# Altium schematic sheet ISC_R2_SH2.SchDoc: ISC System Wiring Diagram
size C; DrawnBy: Filiberto Clara; Engineer: Filiberto Clara; Organization: LIGO Laboratory; Address1: California Institute of Technology; Address2: Massachusetts Institute of Technology; SheetNumber: 14; SheetTotal: 37
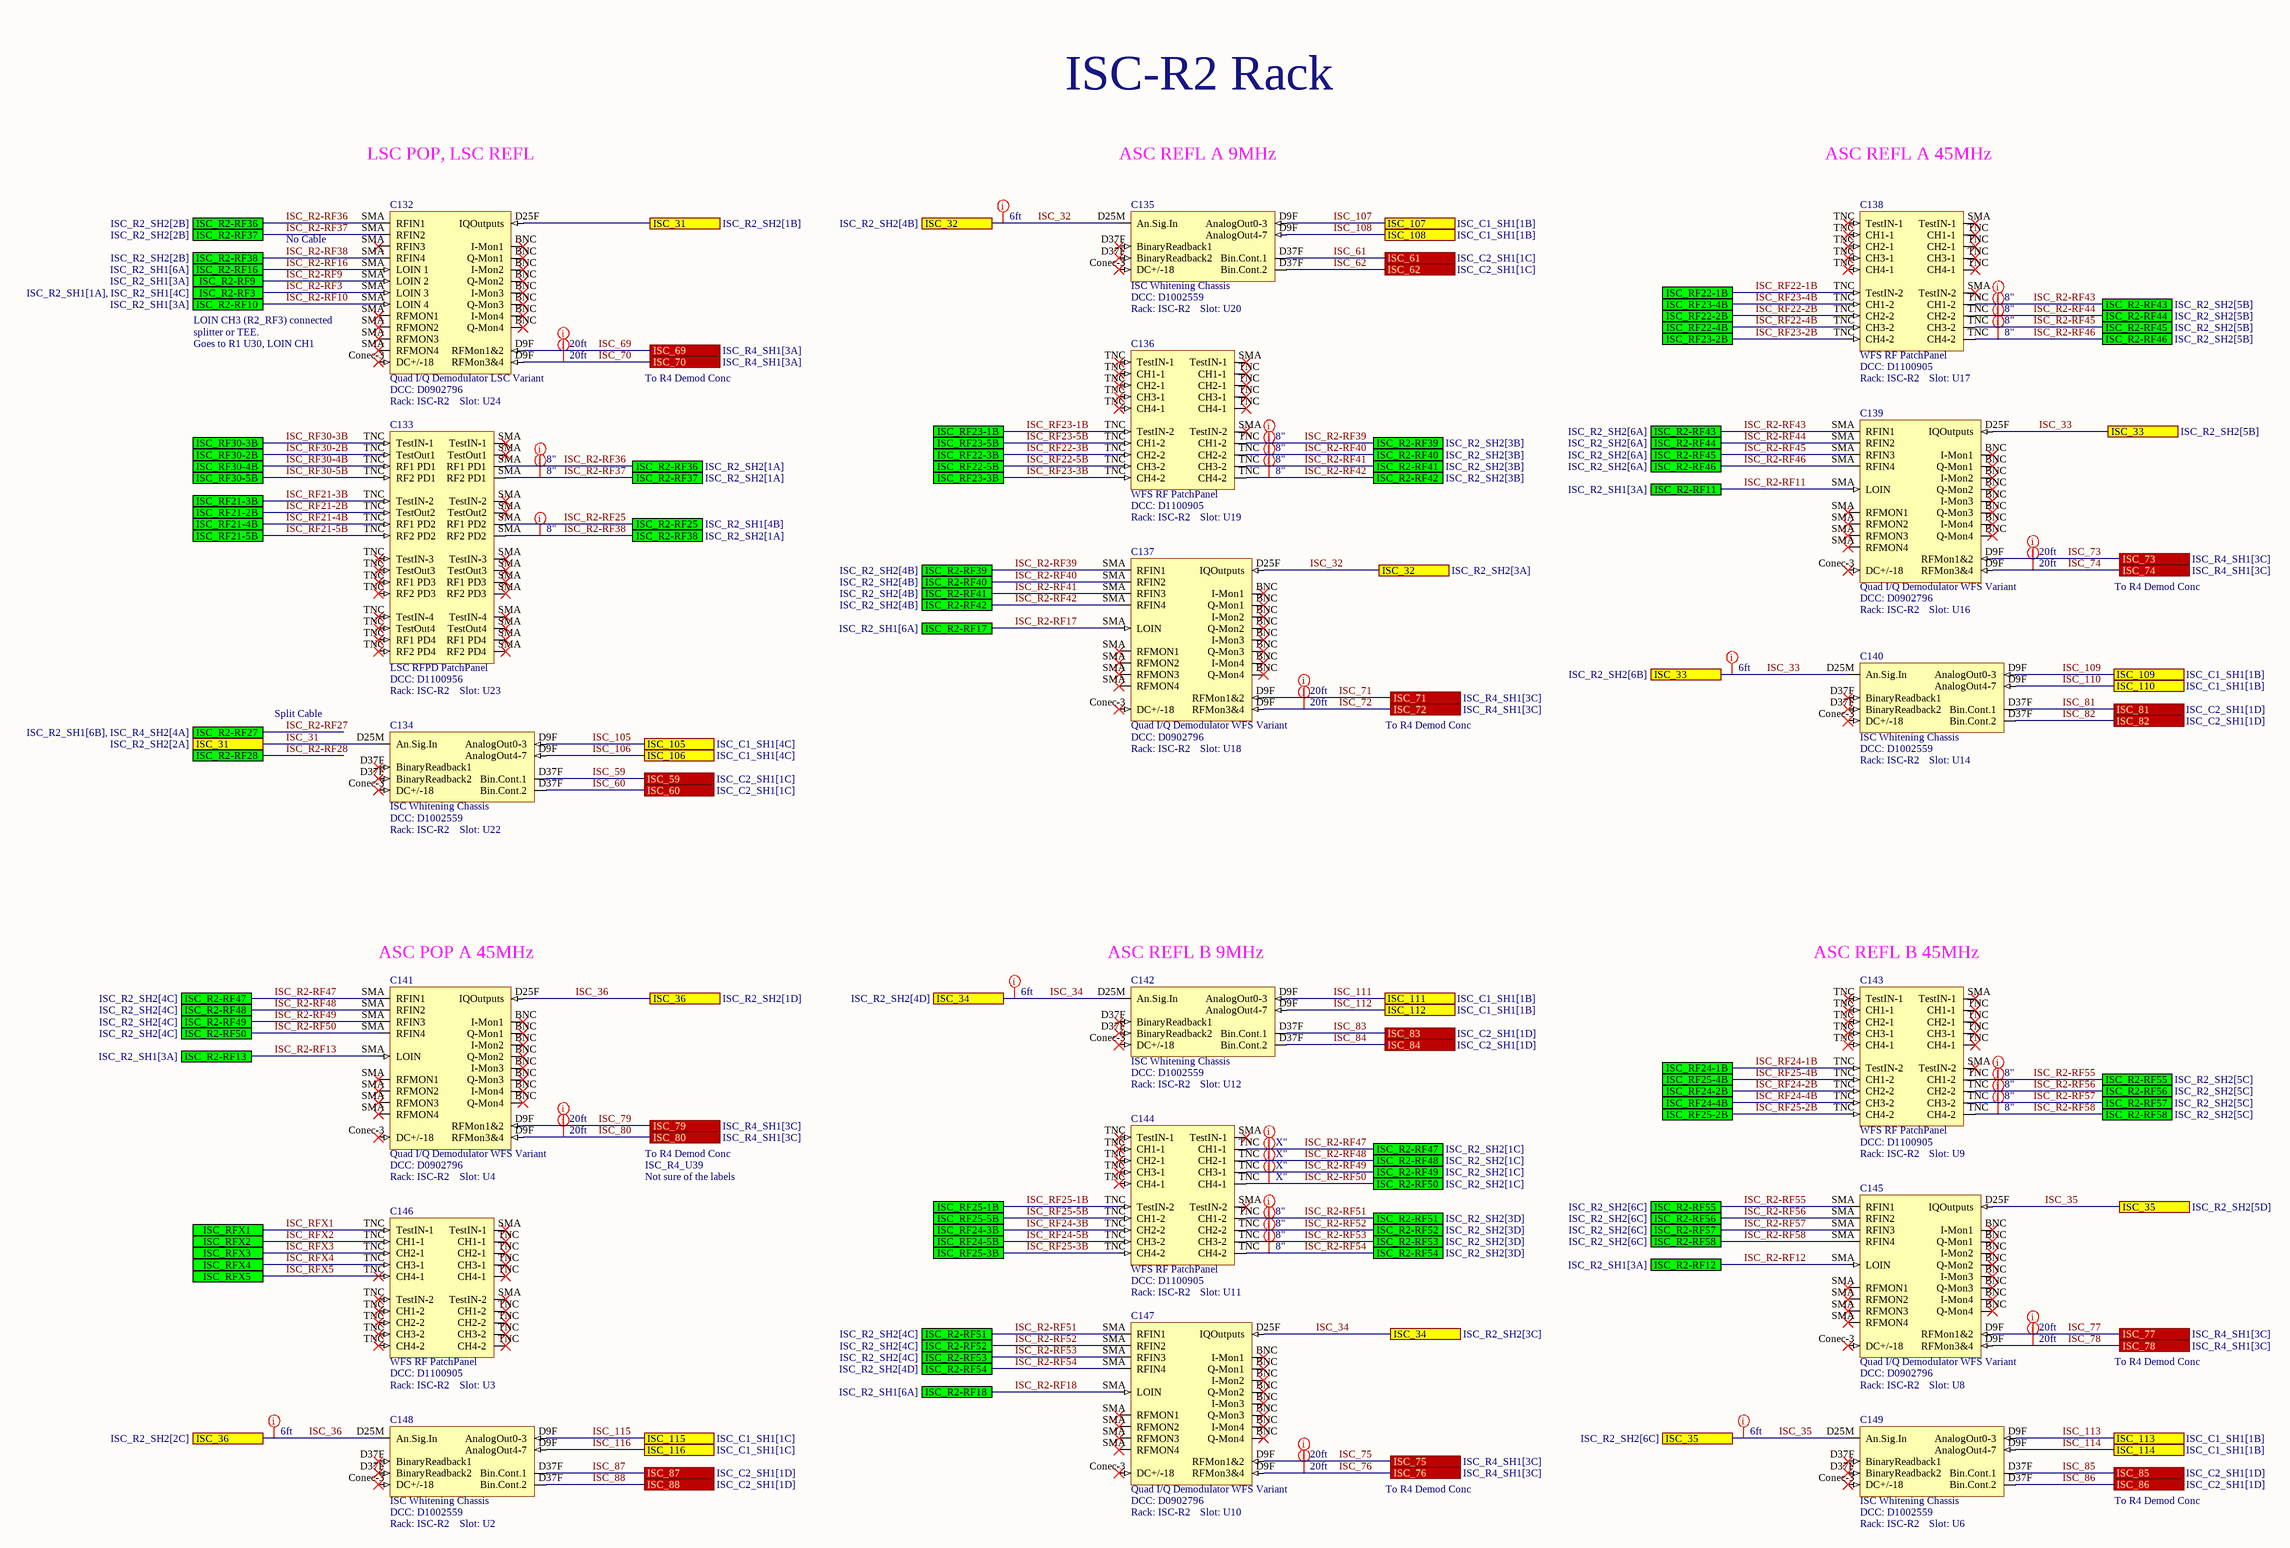
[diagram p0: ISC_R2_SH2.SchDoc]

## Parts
C132  Quad I/Q Demodulator LSC Variant  DCC: D0902796  Rack: ISC-R2  Slot: U24
C133  LSC RFPD PatchPanel  DCC: D1100956  Rack: ISC-R2  Slot: U23
C134  ISC Whitening Chassis  DCC: D1002559  Rack: ISC-R2  Slot: U22
C135  ISC Whitening Chassis  DCC: D1002559  Rack: ISC-R2  Slot: U20
C136  WFS RF PatchPanel  DCC: D1100905  Rack: ISC-R2  Slot: U19
C137  Quad I/Q Demodulator WFS Variant  DCC: D0902796  Rack: ISC-R2  Slot: U18
C138  WFS RF PatchPanel  DCC: D1100905  Rack: ISC-R2  Slot: U17
C139  Quad I/Q Demodulator WFS Variant  DCC: D0902796  Rack: ISC-R2  Slot: U16
C140  ISC Whitening Chassis  DCC: D1002559  Rack: ISC-R2  Slot: U14
C141  Quad I/Q Demodulator WFS Variant  DCC: D0902796  Rack: ISC-R2  Slot: U4
C142  ISC Whitening Chassis  DCC: D1002559  Rack: ISC-R2  Slot: U12
C143  WFS RF PatchPanel  DCC: D1100905  Rack: ISC-R2  Slot: U9
C144  WFS RF PatchPanel  DCC: D1100905  Rack: ISC-R2  Slot: U11
C145  Quad I/Q Demodulator WFS Variant  DCC: D0902796  Rack: ISC-R2  Slot: U8
C146  WFS RF PatchPanel  DCC: D1100905  Rack: ISC-R2  Slot: U3
C147  Quad I/Q Demodulator WFS Variant  DCC: D0902796  Rack: ISC-R2  Slot: U10
C148  ISC Whitening Chassis  DCC: D1002559  Rack: ISC-R2  Slot: U2
C149  ISC Whitening Chassis  DCC: D1002559  Rack: ISC-R2  Slot: U6

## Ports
ISC_31 (see ISC_R2_SH2[1B]), ISC_31 (see ISC_R2_SH2[2A]), ISC_32 (see ISC_R2_SH2[3A]), ISC_32 (see ISC_R2_SH2[4B]), ISC_33 (see ISC_R2_SH2[5B]), ISC_33 (see ISC_R2_SH2[6B]), ISC_34 (see ISC_R2_SH2[3C]), ISC_34 (see ISC_R2_SH2[4D]), ISC_35 (see ISC_R2_SH2[5D]), ISC_35 (see ISC_R2_SH2[6C]), ISC_36 (see ISC_R2_SH2[1D]), ISC_36 (see ISC_R2_SH2[2C]), ISC_59 (see ISC_C2_SH1[1C]), ISC_60 (see ISC_C2_SH1[1C]), ISC_61 (see ISC_C2_SH1[1C]), ISC_62 (see ISC_C2_SH1[1C]), ISC_69 (see ISC_R4_SH1[3A]), ISC_70 (see ISC_R4_SH1[3A]), ISC_71 (see ISC_R4_SH1[3C]), ISC_72 (see ISC_R4_SH1[3C]), ISC_73 (see ISC_R4_SH1[3C]), ISC_74 (see ISC_R4_SH1[3C]), ISC_75 (see ISC_R4_SH1[3C]), ISC_76 (see ISC_R4_SH1[3C]), ISC_77 (see ISC_R4_SH1[3C]), ISC_78 (see ISC_R4_SH1[3C]), ISC_79 (see ISC_R4_SH1[3C]), ISC_80 (see ISC_R4_SH1[3C]), ISC_81 (see ISC_C2_SH1[1D]), ISC_82 (see ISC_C2_SH1[1D]), ISC_83 (see ISC_C2_SH1[1D]), ISC_84 (see ISC_C2_SH1[1D]), ISC_85 (see ISC_C2_SH1[1D]), ISC_86 (see ISC_C2_SH1[1D]), ISC_87 (see ISC_C2_SH1[1D]), ISC_88 (see ISC_C2_SH1[1D]), ISC_105 (see ISC_C1_SH1[4C]), ISC_106 (see ISC_C1_SH1[4C]), ISC_107 (see ISC_C1_SH1[1B]), ISC_108 (see ISC_C1_SH1[1B]), ISC_109 (see ISC_C1_SH1[1B]), ISC_110 (see ISC_C1_SH1[1B]), ISC_111 (see ISC_C1_SH1[1B]), ISC_112 (see ISC_C1_SH1[1B]), ISC_113 (see ISC_C1_SH1[1B]), ISC_114 (see ISC_C1_SH1[1B]), ISC_115 (see ISC_C1_SH1[1C]), ISC_116 (see ISC_C1_SH1[1C]), ISC_R2-RF3 (see ISC_R2_SH1[1A], ISC_R2_SH1[4C]), ISC_R2-RF9 (see ISC_R2_SH1[3A]), ISC_R2-RF10 (see ISC_R2_SH1[3A]), ISC_R2-RF11 (see ISC_R2_SH1[3A]), ISC_R2-RF12 (see ISC_R2_SH1[3A]), ISC_R2-RF13 (see ISC_R2_SH1[3A]), ISC_R2-RF16 (see ISC_R2_SH1[6A]), ISC_R2-RF17 (see ISC_R2_SH1[6A]), ISC_R2-RF18 (see ISC_R2_SH1[6A]), ISC_R2-RF25 (see ISC_R2_SH1[4B]), ISC_R2-RF27 (see ISC_R2_SH1[6B], ISC_R4_SH2[4A]), ISC_R2-RF28, ISC_R2-RF36 (see ISC_R2_SH2[1A]), ISC_R2-RF36 (see ISC_R2_SH2[2B]), ISC_R2-RF37 (see ISC_R2_SH2[1A]), ISC_R2-RF37 (see ISC_R2_SH2[2B]), ISC_R2-RF38 (see ISC_R2_SH2[1A]), ISC_R2-RF38 (see ISC_R2_SH2[2B]), ISC_R2-RF39 (see ISC_R2_SH2[3B]), ISC_R2-RF39 (see ISC_R2_SH2[4B]), ISC_R2-RF40 (see ISC_R2_SH2[3B]), ISC_R2-RF40 (see ISC_R2_SH2[4B]), ISC_R2-RF41 (see ISC_R2_SH2[3B]), ISC_R2-RF41 (see ISC_R2_SH2[4B]), ISC_R2-RF42 (see ISC_R2_SH2[3B]), ISC_R2-RF42 (see ISC_R2_SH2[4B]), ISC_R2-RF43 (see ISC_R2_SH2[5B]), ISC_R2-RF43 (see ISC_R2_SH2[6A]), ISC_R2-RF44 (see ISC_R2_SH2[5B]), ISC_R2-RF44 (see ISC_R2_SH2[6A]), ISC_R2-RF45 (see ISC_R2_SH2[5B]), ISC_R2-RF45 (see ISC_R2_SH2[6A]), ISC_R2-RF46 (see ISC_R2_SH2[5B]), ISC_R2-RF46 (see ISC_R2_SH2[6A]), ISC_R2-RF47 (see ISC_R2_SH2[1C]), ISC_R2-RF47 (see ISC_R2_SH2[4C]), ISC_R2-RF48 (see ISC_R2_SH2[1C]), ISC_R2-RF48 (see ISC_R2_SH2[4C]), ISC_R2-RF49 (see ISC_R2_SH2[1C]), ISC_R2-RF49 (see ISC_R2_SH2[4C]), ISC_R2-RF50 (see ISC_R2_SH2[1C]), ISC_R2-RF50 (see ISC_R2_SH2[4C]), ISC_R2-RF51 (see ISC_R2_SH2[3D]), ISC_R2-RF51 (see ISC_R2_SH2[4C]), ISC_R2-RF52 (see ISC_R2_SH2[3D]), ISC_R2-RF52 (see ISC_R2_SH2[4C]), ISC_R2-RF53 (see ISC_R2_SH2[3D]), ISC_R2-RF53 (see ISC_R2_SH2[4C]), ISC_R2-RF54 (see ISC_R2_SH2[3D]), ISC_R2-RF54 (see ISC_R2_SH2[4D]), ISC_R2-RF55 (see ISC_R2_SH2[5C]), ISC_R2-RF55 (see ISC_R2_SH2[6C]), ISC_R2-RF56 (see ISC_R2_SH2[5C]), ISC_R2-RF56 (see ISC_R2_SH2[6C]), ISC_R2-RF57 (see ISC_R2_SH2[5C]), ISC_R2-RF57 (see ISC_R2_SH2[6C]), ISC_R2-RF58 (see ISC_R2_SH2[5C]), ISC_R2-RF58 (see ISC_R2_SH2[6C]), ISC_RF21-2B, ISC_RF21-3B, ISC_RF21-4B, ISC_RF21-5B, ISC_RF22-1B, ISC_RF22-2B, ISC_RF22-3B, ISC_RF22-4B, ISC_RF22-5B, ISC_RF23-1B, ISC_RF23-2B, ISC_RF23-3B, ISC_RF23-4B, ISC_RF23-5B, ISC_RF24-1B, ISC_RF24-2B, ISC_RF24-3B, ISC_RF24-4B, ISC_RF24-5B, ISC_RF25-1B, ISC_RF25-2B, ISC_RF25-3B, ISC_RF25-4B, ISC_RF25-5B, ISC_RF30-2B, ISC_RF30-3B, ISC_RF30-4B, ISC_RF30-5B, ISC_RFX1, ISC_RFX2, ISC_RFX3, ISC_RFX4, ISC_RFX5

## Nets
ISC_31: C132.D25F(IQOutputs) C134.D25M(An.Sig.In) ; port ISC_31
ISC_32: C135.D25M(An.Sig.In) C137.D25F(IQOutputs) ; port ISC_32
ISC_33: C139.D25F(IQOutputs) C140.D25M(An.Sig.In) ; port ISC_33
ISC_34: C142.D25M(An.Sig.In) C147.D25F(IQOutputs) ; port ISC_34
ISC_35: C145.D25F(IQOutputs) C149.D25M(An.Sig.In) ; port ISC_35
ISC_36: C141.D25F(IQOutputs) C148.D25M(An.Sig.In) ; port ISC_36
ISC_59: C134.D37F(BinaryReadback1) ; port ISC_59
ISC_60: C134.D37F(Bin.Cont.2) ; port ISC_60
ISC_61: C135.D37F(BinaryReadback1) ; port ISC_61
ISC_62: C135.D37F(Bin.Cont.2) ; port ISC_62
ISC_69: C132.D9F(RFMon1&2) ; port ISC_69
ISC_70: C132.D9F(RFMon3&4) ; port ISC_70
ISC_71: C137.D9F(RFMon1&2) ; port ISC_71
ISC_72: C137.D9F(RFMon3&4) ; port ISC_72
ISC_73: C139.D9F(RFMon1&2) ; port ISC_73
ISC_74: C139.D9F(RFMon3&4) ; port ISC_74
ISC_75: C147.D9F(RFMon1&2) ; port ISC_75
ISC_76: C147.D9F(RFMon3&4) ; port ISC_76
ISC_77: C145.D9F(RFMon1&2) ; port ISC_77
ISC_78: C145.D9F(RFMon3&4) ; port ISC_78
ISC_79: C141.D9F(RFMon1&2) ; port ISC_79
ISC_80: C141.D9F(RFMon3&4) ; port ISC_80
ISC_81: C140.D37F(BinaryReadback1) ; port ISC_81
ISC_82: C140.D37F(Bin.Cont.2) ; port ISC_82
ISC_83: C142.D37F(BinaryReadback1) ; port ISC_83
ISC_84: C142.D37F(Bin.Cont.2) ; port ISC_84
ISC_85: C149.D37F(BinaryReadback1) ; port ISC_85
ISC_86: C149.D37F(Bin.Cont.2) ; port ISC_86
ISC_87: C148.D37F(BinaryReadback1) ; port ISC_87
ISC_88: C148.D37F(Bin.Cont.2) ; port ISC_88
ISC_105: C134.D9F(AnalogOut0-3) ; port ISC_105
ISC_106: C134.D9F(AnalogOut4-7) ; port ISC_106
ISC_107: C135.D9F(AnalogOut0-3) ; port ISC_107
ISC_108: C135.D9F(AnalogOut4-7) ; port ISC_108
ISC_109: C140.D9F(AnalogOut0-3) ; port ISC_109
ISC_110: C140.D9F(AnalogOut4-7) ; port ISC_110
ISC_111: C142.D9F(AnalogOut0-3) ; port ISC_111
ISC_112: C142.D9F(AnalogOut4-7) ; port ISC_112
ISC_113: C149.D9F(AnalogOut0-3) ; port ISC_113
ISC_114: C149.D9F(AnalogOut4-7) ; port ISC_114
ISC_115: C148.D9F(AnalogOut0-3) ; port ISC_115
ISC_116: C148.D9F(AnalogOut4-7) ; port ISC_116
ISC_R2-RF3: C132.SMA(LOIN_3) ; port ISC_R2-RF3
ISC_R2-RF9: C132.SMA(LOIN_2) ; port ISC_R2-RF9
ISC_R2-RF10: C132.SMA(LOIN_4) ; port ISC_R2-RF10
ISC_R2-RF11: C139.SMA(LOIN) ; port ISC_R2-RF11
ISC_R2-RF12: C145.SMA(LOIN) ; port ISC_R2-RF12
ISC_R2-RF13: C141.SMA(LOIN) ; port ISC_R2-RF13
ISC_R2-RF16: C132.SMA(LOIN_1) ; port ISC_R2-RF16
ISC_R2-RF17: C137.SMA(LOIN) ; port ISC_R2-RF17
ISC_R2-RF18: C147.SMA(LOIN) ; port ISC_R2-RF18
ISC_R2-RF25: C133.SMA(RF1_PD2) ; port ISC_R2-RF25
ISC_R2-RF36: C132.SMA(RFIN1) C133.SMA(TestIN-1) ; port ISC_R2-RF36
ISC_R2-RF37: C132.SMA(RFIN2) C133.SMA(RF2_PD1) ; port ISC_R2-RF37
ISC_R2-RF38: C132.SMA(RFIN4) C133.SMA(RF2_PD2) ; port ISC_R2-RF38
ISC_R2-RF39: C136.TNC(CH1-2) C137.SMA(RFIN1) ; port ISC_R2-RF39
ISC_R2-RF40: C136.TNC(CH2-2) C137.SMA(RFIN2) ; port ISC_R2-RF40
ISC_R2-RF41: C136.TNC(CH3-2) C137.SMA(RFIN3) ; port ISC_R2-RF41
ISC_R2-RF42: C136.TNC(CH4-2) C137.SMA(RFIN4) ; port ISC_R2-RF42
ISC_R2-RF43: C138.TNC(CH1-2) C139.SMA(RFIN1) ; port ISC_R2-RF43
ISC_R2-RF44: C138.TNC(CH2-2) C139.SMA(RFIN2) ; port ISC_R2-RF44
ISC_R2-RF45: C138.TNC(CH3-2) C139.SMA(RFIN3) ; port ISC_R2-RF45
ISC_R2-RF46: C138.TNC(CH4-2) C139.SMA(RFIN4) ; port ISC_R2-RF46
ISC_R2-RF47: C141.SMA(RFIN1) C144.TNC(CH1-1) ; port ISC_R2-RF47
ISC_R2-RF48: C141.SMA(RFIN2) C144.TNC(CH2-1) ; port ISC_R2-RF48
ISC_R2-RF49: C141.SMA(RFIN3) C144.TNC(CH3-1) ; port ISC_R2-RF49
ISC_R2-RF50: C141.SMA(RFIN4) C144.TNC(CH4-1) ; port ISC_R2-RF50
ISC_R2-RF51: C144.TNC(CH1-2) C147.SMA(RFIN1) ; port ISC_R2-RF51
ISC_R2-RF52: C144.TNC(CH2-2) C147.SMA(RFIN2) ; port ISC_R2-RF52
ISC_R2-RF53: C144.TNC(CH3-2) C147.SMA(RFIN3) ; port ISC_R2-RF53
ISC_R2-RF54: C144.TNC(CH4-2) C147.SMA(RFIN4) ; port ISC_R2-RF54
ISC_R2-RF55: C143.TNC(CH1-2) C145.SMA(RFIN1) ; port ISC_R2-RF55
ISC_R2-RF56: C143.TNC(CH2-2) C145.SMA(RFIN2) ; port ISC_R2-RF56
ISC_R2-RF57: C143.TNC(CH3-2) C145.SMA(RFIN3) ; port ISC_R2-RF57
ISC_R2-RF58: C143.TNC(CH4-2) C145.SMA(RFIN4) ; port ISC_R2-RF58
ISC_RF21-2B: C133.TNC(TestOut2) ; port ISC_RF21-2B
ISC_RF21-3B: C133.TNC(TestIN-2) ; port ISC_RF21-3B
ISC_RF21-4B: C133.TNC(RF1_PD2) ; port ISC_RF21-4B
ISC_RF21-5B: C133.TNC(RF2_PD2) ; port ISC_RF21-5B
ISC_RF22-1B: C138.TNC(TestIN-1) ; port ISC_RF22-1B
ISC_RF22-2B: C138.TNC(CH2-2) ; port ISC_RF22-2B
ISC_RF22-3B: C136.TNC(CH2-2) ; port ISC_RF22-3B
ISC_RF22-4B: C138.TNC(CH3-2) ; port ISC_RF22-4B
ISC_RF22-5B: C136.TNC(CH3-2) ; port ISC_RF22-5B
ISC_RF23-1B: C136.TNC(TestIN-1) ; port ISC_RF23-1B
ISC_RF23-2B: C138.TNC(CH4-2) ; port ISC_RF23-2B
ISC_RF23-3B: C136.TNC(CH4-2) ; port ISC_RF23-3B
ISC_RF23-4B: C138.TNC(CH1-2) ; port ISC_RF23-4B
ISC_RF23-5B: C136.TNC(CH1-2) ; port ISC_RF23-5B
ISC_RF24-1B: C143.TNC(TestIN-1) ; port ISC_RF24-1B
ISC_RF24-2B: C143.TNC(CH2-2) ; port ISC_RF24-2B
ISC_RF24-3B: C144.TNC(CH2-2) ; port ISC_RF24-3B
ISC_RF24-4B: C143.TNC(CH3-2) ; port ISC_RF24-4B
ISC_RF24-5B: C144.TNC(CH3-2) ; port ISC_RF24-5B
ISC_RF25-1B: C144.TNC(TestIN-1) ; port ISC_RF25-1B
ISC_RF25-2B: C143.TNC(CH4-2) ; port ISC_RF25-2B
ISC_RF25-3B: C144.TNC(CH4-2) ; port ISC_RF25-3B
ISC_RF25-4B: C143.TNC(CH1-2) ; port ISC_RF25-4B
ISC_RF25-5B: C144.TNC(CH1-2) ; port ISC_RF25-5B
ISC_RF30-2B: C133.TNC(TestOut1) ; port ISC_RF30-2B
ISC_RF30-3B: C133.TNC(TestIN-1) ; port ISC_RF30-3B
ISC_RF30-4B: C133.TNC(RF1_PD1) ; port ISC_RF30-4B
ISC_RF30-5B: C133.TNC(RF2_PD1) ; port ISC_RF30-5B
ISC_RFX1: C146.TNC(TestIN-1) ; port ISC_RFX1
ISC_RFX2: C146.TNC(CH1-1) ; port ISC_RFX2
ISC_RFX3: C146.TNC(CH2-1) ; port ISC_RFX3
ISC_RFX4: C146.TNC(CH3-1) ; port ISC_RFX4
ISC_RFX5: C146.TNC(CH4-1) ; port ISC_RFX5

Not connected (* = marked no-connect by the designer): C132 BNC(I-Mon1)* Conec-3(DC+/-18)*; C134 Conec-3(DC+/-18)*; C135 Conec-3(DC+/-18)*; C136 SMA(TestIN-1)*; C137 BNC(I-Mon1)* Conec-3(DC+/-18)*; C138 SMA(TestIN-1)*; C139 BNC(I-Mon1)* Conec-3(DC+/-18)*; C140 Conec-3(DC+/-18)*; C141 BNC(I-Mon1)* Conec-3(DC+/-18)*; C142 Conec-3(DC+/-18)*; C143 SMA(TestIN-1)*; C144 SMA(TestIN-1)*; C145 BNC(I-Mon1)* Conec-3(DC+/-18)*; C146 SMA(TestIN-1)*; C147 BNC(I-Mon1)* Conec-3(DC+/-18)*; C148 Conec-3(DC+/-18)*; C149 Conec-3(DC+/-18)*

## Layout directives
Length: 6ft: ISC_32, ISC_33, ISC_34, ISC_35, ISC_36
Length: 20ft: ISC_69, ISC_70, ISC_71, ISC_72, ISC_73, ISC_74, ISC_75, ISC_76, ISC_77, ISC_78, ISC_79, ISC_80
Length: 8": ISC_R2-RF36, ISC_R2-RF37, ISC_R2-RF38, ISC_R2-RF39, ISC_R2-RF40, ISC_R2-RF41, ISC_R2-RF42, ISC_R2-RF43, ISC_R2-RF44, ISC_R2-RF45, ISC_R2-RF46, ISC_R2-RF51, ISC_R2-RF52, ISC_R2-RF53, ISC_R2-RF54, ISC_R2-RF55, ISC_R2-RF56, ISC_R2-RF57, ISC_R2-RF58
Length: X": ISC_R2-RF47, ISC_R2-RF48, ISC_R2-RF49, ISC_R2-RF50

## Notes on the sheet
- ISC-R2 Rack
- LSC POP, LSC REFL
- ASC REFL A 9MHz
- ASC REFL A 45MHz
- No Cable
- LOIN CH3 (R2_RF3) connected
- splitter or TEE.
- Goes to R1 U30, LOIN CH1
- To R4 Demod Conc
- Split Cable
- (near C141) ASC POP A 45MHz
- (near C142) ASC REFL B 9MHz
- (near C143) ASC REFL B 45MHz
- ISC_R4_U39
- Not sure of the labels

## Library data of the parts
C132 = QuadIQdemod_LSC: Serial: Sxxxxxxx; System: ISC
C133 = LSC RFPD PatchPanel: Serial: Sxxxxxxx; System: ISC
C134 C135 C140 C142 C148 C149 = ISC Whitening: Serial: Sxxxxxxx
C136 C138 C143 C144 C146 = WFS RFPD PatchPanel: Serial: Sxxxxxxx; System: ISC
C137 C139 C141 C145 C147 = QuadIQdemod_WFS: Serial: Sxxxxxxx; System: ISC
